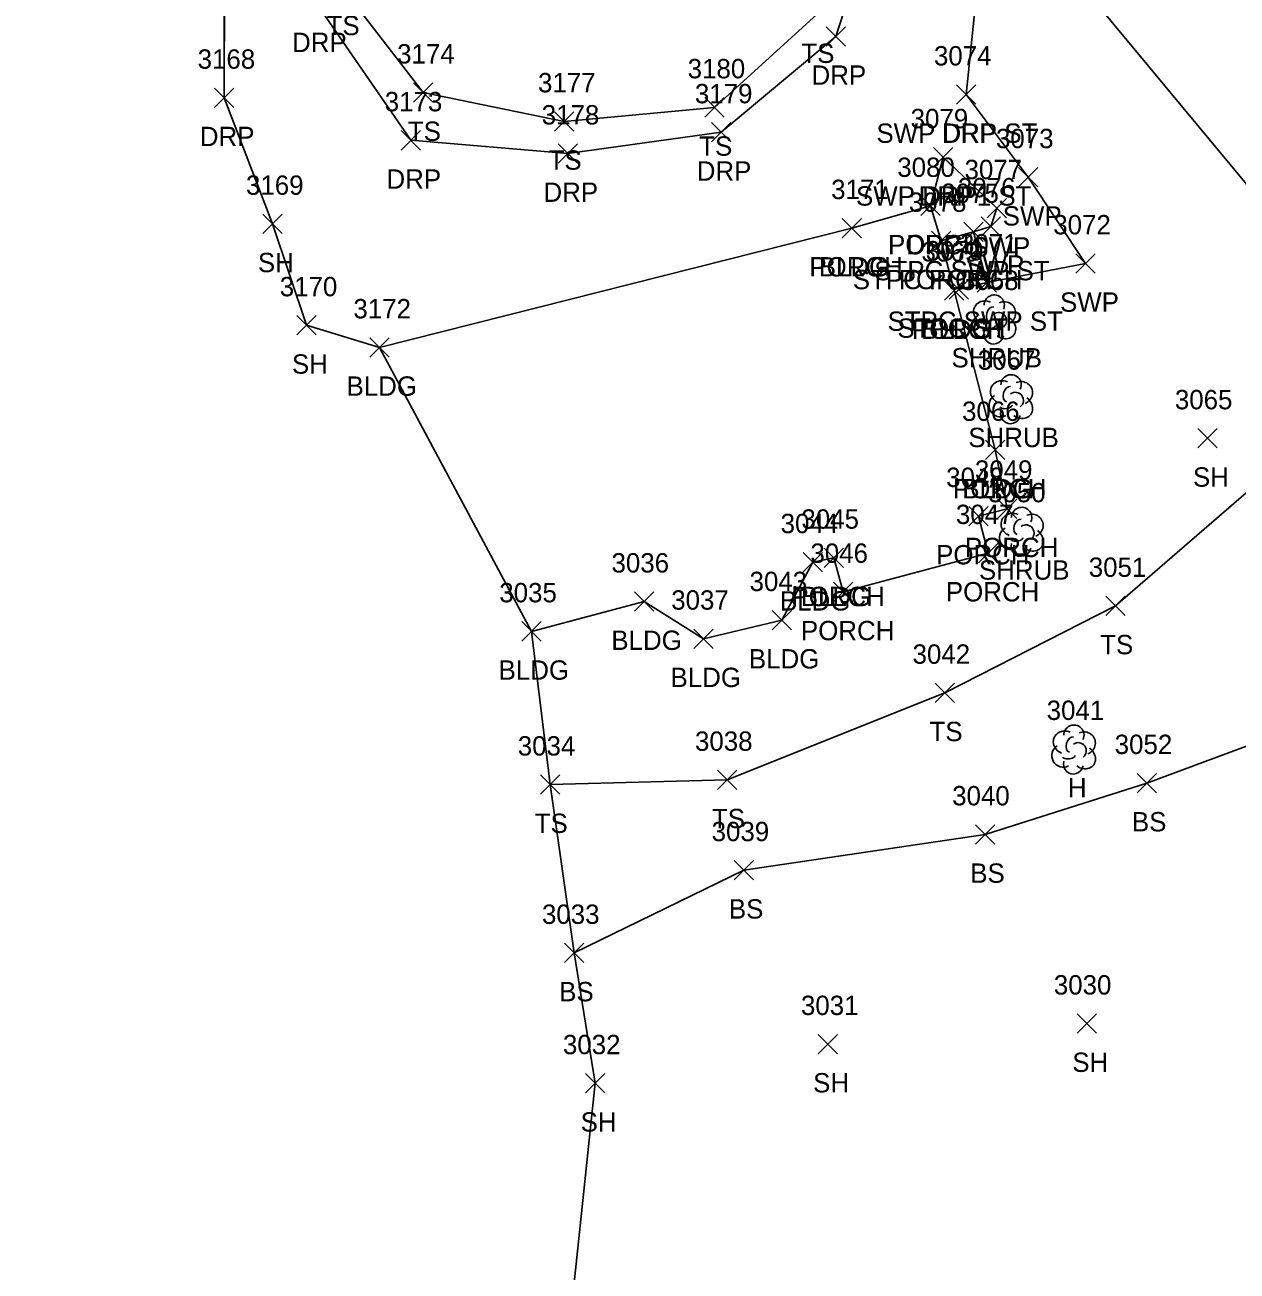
# Model space of a CAD drawing. Extents: x 1509053 to 1511576, y 400838 to 402572.
# Drawn here: x 1509560.1 to 1509685.4, y 401585.4 to 401714.2 of the extents above; entities that cross this region are included whole.
import ezdxf

# ---------------------------------------------------------------- set-up
doc = ezdxf.new("R2010")
doc.units = 0
for name, color, linetype in [('L_A', 7, 'Continuous'), ('L_I', 7, 'Continuous'), ('L_TIC', 7, 'Continuous'), ('LAWA', 7, 'Continuous'), ('LBC', 7, 'Continuous'), ('LBF', 7, 'Continuous'), ('LELB', 7, 'Continuous'), ('LSH', 7, 'Continuous'), ('LSOGP', 7, 'Continuous'), ('LTD', 7, 'Continuous'), ('R_A', 7, 'Continuous'), ('R_I', 7, 'Continuous'), ('R_TIC', 7, 'Continuous'), ('RDP', 7, 'Continuous'), ('RSW', 7, 'Continuous')]:
    doc.layers.add(name, color=color, linetype=linetype)

msp = doc.modelspace()

# ---------------------------------------------------------------- linework, layer by layer
at = {"layer": 'L_TIC'}
for points in [[(1509600.28, 401706.22), (1509602.28, 401708.22)], [(1509602.28, 401706.22), (1509600.28, 401708.22)], [(1509630.39, 401704.69), (1509632.39, 401706.69)], [(1509632.39, 401704.69), (1509630.39, 401706.69)], [(1509614.83, 401703.24), (1509616.83, 401705.24)], [(1509616.83, 401703.24), (1509614.83, 401705.24)], [(1509652.7, 401694.5), (1509654.7, 401696.5)], [(1509654.7, 401694.5), (1509652.7, 401696.5)], [(1509584.71, 401692.65), (1509586.71, 401694.65)], [(1509586.71, 401692.65), (1509584.71, 401694.65)], [(1509644.57, 401692.21), (1509646.57, 401694.21)], [(1509646.57, 401692.21), (1509644.57, 401694.21)], [(1509644.57, 401692.21), (1509646.57, 401694.21)], [(1509646.57, 401692.21), (1509644.57, 401694.21)], [(1509657.16, 401691.81), (1509659.16, 401693.81)], [(1509659.16, 401691.81), (1509657.16, 401693.81)], [(1509653.82, 401690.89), (1509655.82, 401692.89)], [(1509655.82, 401690.89), (1509653.82, 401692.89)], [(1509653.82, 401690.89), (1509655.82, 401692.89)], [(1509655.82, 401690.89), (1509653.82, 401692.89)], [(1509655.65, 401685.87), (1509657.65, 401687.87)], [(1509657.65, 401685.87), (1509655.65, 401687.87)], [(1509658.53, 401686.59), (1509660.53, 401688.59)], [(1509660.53, 401686.59), (1509658.53, 401688.59)], [(1509655.17, 401685.76), (1509657.17, 401687.76)], [(1509657.17, 401685.76), (1509655.17, 401687.76)], [(1509655.17, 401685.76), (1509657.17, 401687.76)], [(1509657.17, 401685.76), (1509655.17, 401687.76)], [(1509588.22, 401682.16), (1509590.22, 401684.16)], [(1509590.22, 401682.16), (1509588.22, 401684.16)], [(1509595.75, 401679.88), (1509597.75, 401681.88)], [(1509597.75, 401679.88), (1509595.75, 401681.88)], [(1509681.35, 401670.48), (1509683.35, 401672.48)], [(1509683.35, 401670.48), (1509681.35, 401672.48)], [(1509659.41, 401669.28), (1509661.41, 401671.28)], [(1509661.41, 401669.28), (1509659.41, 401671.28)], [(1509659.41, 401669.28), (1509661.41, 401671.28)], [(1509661.41, 401669.28), (1509659.41, 401671.28)], [(1509660.65, 401663.2), (1509662.65, 401665.2)], [(1509662.65, 401663.2), (1509660.65, 401665.2)], [(1509657.67, 401662.45), (1509659.67, 401664.45)], [(1509659.67, 401662.45), (1509657.67, 401664.45)], [(1509640.56, 401657.68), (1509642.56, 401659.68)], [(1509642.56, 401657.68), (1509640.56, 401659.68)], [(1509642.71, 401658.14), (1509644.71, 401660.14)], [(1509644.71, 401658.14), (1509642.71, 401660.14)], [(1509642.71, 401658.14), (1509644.71, 401660.14)], [(1509644.71, 401658.14), (1509642.71, 401660.14)], [(1509658.68, 401658.62), (1509660.68, 401660.62)], [(1509660.68, 401658.62), (1509658.68, 401660.62)], [(1509643.7, 401654.61), (1509645.7, 401656.61)], [(1509645.7, 401654.61), (1509643.7, 401656.61)], [(1509623.13, 401653.61), (1509625.13, 401655.61)], [(1509625.13, 401653.61), (1509623.13, 401655.61)], [(1509671.84, 401653.16), (1509673.84, 401655.16)], [(1509673.84, 401653.16), (1509671.84, 401655.16)], [(1509637.35, 401651.69), (1509639.35, 401653.69)], [(1509639.35, 401651.69), (1509637.35, 401653.69)], [(1509611.48, 401650.53), (1509613.48, 401652.53)], [(1509613.48, 401650.53), (1509611.48, 401652.53)], [(1509629.25, 401649.77), (1509631.25, 401651.77)], [(1509631.25, 401649.77), (1509629.25, 401651.77)], [(1509654.2, 401644.18), (1509656.2, 401646.18)], [(1509656.2, 401644.18), (1509654.2, 401646.18)], [(1509613.39, 401634.69), (1509615.39, 401636.69)], [(1509615.39, 401634.69), (1509613.39, 401636.69)], [(1509631.71, 401635.18), (1509633.71, 401637.18)], [(1509633.71, 401635.18), (1509631.71, 401637.18)], [(1509675.08, 401634.85), (1509677.08, 401636.85)], [(1509677.08, 401634.85), (1509675.08, 401636.85)], [(1509658.37, 401629.54), (1509660.37, 401631.54)], [(1509660.37, 401629.54), (1509658.37, 401631.54)], [(1509633.43, 401625.84), (1509635.43, 401627.84)], [(1509635.43, 401625.84), (1509633.43, 401627.84)], [(1509615.88, 401617.29), (1509617.88, 401619.29)], [(1509617.88, 401617.29), (1509615.88, 401619.29)], [(1509668.88, 401609.99), (1509670.88, 401611.99)], [(1509670.88, 401609.99), (1509668.88, 401611.99)], [(1509642.09, 401607.87), (1509644.09, 401609.87)], [(1509644.09, 401607.87), (1509642.09, 401609.87)], [(1509618.06, 401603.82), (1509620.06, 401605.82)], [(1509620.06, 401603.82), (1509618.06, 401605.82)]]:
    msp.add_lwpolyline(points, dxfattribs=at)
at = {"layer": 'LAWA'}
msp.add_lwpolyline([(1509638.88, 401488.13), (1509666.35, 401492.77), (1509693.47, 401489.31), (1509706.73, 401489.66), (1509714.33, 401510.79), (1509715.13, 401545.88), (1509713.34, 401580.23), (1509712.38, 401615.78), (1509710.87, 401643.63), (1509696.77, 401674.88), (1509690.26, 401693.05), (1509667.45, 401720.56), (1509662.48, 401743.44), (1509649.82, 401764.29), (1509628.65, 401784.18), (1509611.29, 401798.2), (1509592.85, 401815.68), (1509576.11, 401831.25), (1509568.72, 401841.78), (1509569.85, 401855.18), (1509582.24, 401868.06), (1509599.14, 401876.59), (1509619.4, 401883.23)], dxfattribs=at)
at = {"layer": 'LBC'}
for points in [[(1509645.57, 401693.21), (1509596.75, 401680.88)], [(1509660.41, 401670.28), (1509656.17, 401686.76)], [(1509612.48, 401651.53), (1509624.13, 401654.61), (1509630.25, 401650.77), (1509638.35, 401652.69), (1509641.56, 401658.68), (1509643.71, 401659.14)]]:
    msp.add_lwpolyline(points, dxfattribs=at)
at = {"layer": 'LBF'}
for points in [[(1509656.17, 401686.76), (1509654.82, 401691.89), (1509653.7, 401695.5), (1509645.57, 401693.21)], [(1509656.65, 401686.87), (1509659.53, 401687.59), (1509658.16, 401692.81), (1509654.82, 401691.89)], [(1509643.71, 401659.14), (1509644.7, 401655.61), (1509659.68, 401659.62), (1509658.67, 401663.45), (1509661.65, 401664.2), (1509660.41, 401670.28)]]:
    msp.add_lwpolyline(points, dxfattribs=at)
at = {"layer": 'LELB'}
for points in [[(1509601.28, 401707.22), (1509615.83, 401704.24), (1509631.39, 401705.69), (1509641.95, 401715.28), (1509646.3, 401727.1), (1509643.65, 401741.92), (1509634.43, 401756.65), (1509616.45, 401773.63), (1509604.1, 401783.09), (1509598.27, 401760.84), (1509593.29, 401737.02), (1509592.88, 401718.15)], [(1509592.88, 401718.15), (1509601.28, 401707.22)], [(1509614.39, 401635.69), (1509632.71, 401636.18), (1509655.2, 401645.18), (1509672.84, 401654.16), (1509696.77, 401674.88)], [(1509616.88, 401618.29), (1509634.43, 401626.84), (1509659.37, 401630.54), (1509676.08, 401635.85), (1509695.63, 401643.11)]]:
    msp.add_lwpolyline(points, dxfattribs=at)
at = {"layer": 'LSH'}
for p, q in [((1509660.25, 401683.81), (1509660.25, 401683.81)), ((1509660.25, 401683.81), (1509660.25, 401683.81)), ((1509661.99, 401675.57), (1509661.99, 401675.57)), ((1509661.99, 401675.57), (1509661.99, 401675.57)), ((1509663.09, 401661.87), (1509663.09, 401661.87)), ((1509663.09, 401661.87), (1509663.09, 401661.87))]:
    msp.add_line(p, q, dxfattribs=at)
for centre in [(1509660.3, 401685.25), (1509662.04, 401677.01), (1509663.13, 401663.3)]:
    msp.add_arc(centre, 1.05, 335.5272, 180.9563, dxfattribs=at)
for centre, major_axis, ratio, start_param, end_param in [((1509659.46, 401684.48), (1.21, -0.51), 0.895232, 1.570796, 4.712389), ((1509661.29, 401684.4), (-1.14, -0.48), 0.949671, 1.570796, 4.712389), ((1509659.17, 401683.1), (0.58, -1.04), 0.959034, 3.141593, 6.283185), ((1509660.04, 401684.27), (-0.208, -0.792), 0.645439, 3.141593, 6.283185), ((1509660.75, 401683.65), (-0.5, 0.667), 0.989748, 3.141593, 6.283185), ((1509659.79, 401683.06), (-0.625, -0.083), 0.423636, 0, 3.141593), ((1509661.25, 401682.98), (-1.09, 0.79), 0.841452, 1.570796, 4.712389), ((1509660.25, 401682.31), (0.26, 1.06), 0.942809, 1.570796, 4.712389), ((1509661.2, 401676.24), (1.21, -0.51), 0.895232, 1.570796, 4.712389), ((1509661.78, 401676.03), (-0.208, -0.792), 0.645439, 3.141593, 6.283185), ((1509662.49, 401675.41), (-0.5, 0.667), 0.989748, 3.141593, 6.283185), ((1509663.03, 401676.16), (-1.14, -0.48), 0.949671, 1.570796, 4.712389), ((1509660.91, 401674.87), (0.58, -1.04), 0.959034, 3.141593, 6.283185), ((1509662.99, 401674.74), (-1.09, 0.79), 0.841452, 1.570796, 4.712389), ((1509661.99, 401674.07), (0.26, 1.06), 0.942809, 1.570796, 4.712389), ((1509661.53, 401674.82), (-0.625, -0.083), 0.423636, 0, 3.141593), ((1509662.3, 401662.53), (1.21, -0.51), 0.895232, 1.570796, 4.712389), ((1509664.13, 401662.45), (-1.14, -0.48), 0.949671, 1.570796, 4.712389), ((1509662, 401661.16), (0.58, -1.04), 0.959034, 3.141593, 6.283185), ((1509662.88, 401662.32), (-0.208, -0.792), 0.645439, 3.141593, 6.283185), ((1509663.59, 401661.7), (-0.5, 0.667), 0.989748, 3.141593, 6.283185), ((1509662.63, 401661.12), (-0.625, -0.083), 0.423636, 0, 3.141593), ((1509664.09, 401661.03), (-1.09, 0.79), 0.841452, 1.570796, 4.712389), ((1509663.09, 401660.37), (0.26, 1.06), 0.942809, 1.570796, 4.712389)]:
    msp.add_ellipse(centre, major_axis=major_axis, ratio=ratio, start_param=start_param, end_param=end_param, dxfattribs=at)
at = {"layer": 'LSOGP'}
msp.add_lwpolyline([(1509580.73, 401718.39), (1509580.72, 401712.53), (1509580.7, 401706.68), (1509585.71, 401693.65), (1509589.22, 401683.16), (1509596.75, 401680.88), (1509612.48, 401651.53), (1509614.39, 401635.69), (1509616.88, 401618.29), (1509619.06, 401604.82), (1509615.52, 401571.4)], dxfattribs=at)
at = {"layer": 'LTD'}
msp.add_line((1509668.49, 401639.37), (1509668.49, 401639.37), dxfattribs=at)
msp.add_line((1509668.49, 401639.37), (1509668.49, 401639.37), dxfattribs=at)
msp.add_arc((1509668.53, 401640.8), 1.05, 335.5272, 180.9563, dxfattribs=at)
for centre, major_axis, ratio, start_param, end_param in [((1509667.7, 401640.03), (1.21, -0.51), 0.895232, 1.570796, 4.712389), ((1509668.28, 401639.82), (-0.208, -0.792), 0.645439, 3.141593, 6.283185), ((1509669.53, 401639.95), (-1.14, -0.48), 0.949671, 1.570796, 4.712389), ((1509667.4, 401638.66), (0.58, -1.04), 0.959034, 3.141593, 6.283185), ((1509668.99, 401639.2), (-0.5, 0.667), 0.989748, 3.141593, 6.283185), ((1509669.49, 401638.53), (-1.09, 0.79), 0.841452, 1.570796, 4.712389), ((1509668.49, 401637.87), (0.26, 1.06), 0.942809, 1.570796, 4.712389), ((1509668.03, 401638.62), (-0.625, -0.083), 0.423636, 0, 3.141593)]:
    msp.add_ellipse(centre, major_axis=major_axis, ratio=ratio, start_param=start_param, end_param=end_param, dxfattribs=at)
at = {"layer": 'R_TIC'}
for points in [[(1509642.93, 401712.02), (1509644.93, 401714.02)], [(1509644.93, 401712.02), (1509642.93, 401714.02)], [(1509579.7, 401705.68), (1509581.7, 401707.68)], [(1509581.7, 401705.68), (1509579.7, 401707.68)], [(1509656.41, 401706.02), (1509658.41, 401708.02)], [(1509658.41, 401706.02), (1509656.41, 401708.02)], [(1509656.41, 401706.02), (1509658.41, 401708.02)], [(1509658.41, 401706.02), (1509656.41, 401708.02)], [(1509631.07, 401702.11), (1509633.07, 401704.11)], [(1509633.07, 401702.11), (1509631.07, 401704.11)], [(1509599, 401701.28), (1509601, 401703.28)], [(1509601, 401701.28), (1509599, 401703.28)], [(1509615.22, 401699.92), (1509617.22, 401701.92)], [(1509617.22, 401699.92), (1509615.22, 401701.92)], [(1509654.01, 401699.53), (1509656.01, 401701.53)], [(1509656.01, 401699.53), (1509654.01, 401701.53)], [(1509654.01, 401699.53), (1509656.01, 401701.53)], [(1509656.01, 401699.53), (1509654.01, 401701.53)], [(1509662.82, 401697.47), (1509664.82, 401699.47)], [(1509664.82, 401697.47), (1509662.82, 401699.47)], [(1509652.7, 401694.5), (1509654.7, 401696.5)], [(1509654.7, 401694.5), (1509652.7, 401696.5)], [(1509659.57, 401694.27), (1509661.57, 401696.27)], [(1509661.57, 401694.27), (1509659.57, 401696.27)], [(1509658.95, 401692.39), (1509660.95, 401694.39)], [(1509660.95, 401692.39), (1509658.95, 401694.39)], [(1509657.16, 401691.81), (1509659.16, 401693.81)], [(1509659.16, 401691.81), (1509657.16, 401693.81)], [(1509668.74, 401688.56), (1509670.74, 401690.56)], [(1509670.74, 401688.56), (1509668.74, 401690.56)], [(1509658.53, 401686.59), (1509660.53, 401688.59)], [(1509660.53, 401686.59), (1509658.53, 401688.59)]]:
    msp.add_lwpolyline(points, dxfattribs=at)
at = {"layer": 'RDP'}
for points in [[(1509572.43, 401913.76), (1509571.87, 401895.84), (1509563.03, 401875.91), (1509553.74, 401858.01), (1509556.14, 401835.6), (1509571.23, 401816.18), (1509583.76, 401803.06), (1509589.35, 401790.3), (1509589.12, 401773.24), (1509584.51, 401748.72), (1509580.76, 401730.09), (1509580.7, 401706.68)], [(1509657.41, 401707.02), (1509658.95, 401722.11), (1509659.43, 401736.67), (1509654.34, 401752.12), (1509646.68, 401762.21), (1509626.54, 401780.34), (1509601.43, 401800.74), (1509589.45, 401812.5), (1509573.07, 401828.07), (1509565.22, 401840.56), (1509563.11, 401852.67), (1509569.22, 401864.7), (1509579.4, 401875.5), (1509597.32, 401883.76), (1509619.81, 401887.87)], [(1509600, 401702.28), (1509616.22, 401700.92), (1509632.07, 401703.11), (1509643.93, 401713.02), (1509648.45, 401726.97), (1509646.97, 401743.37), (1509636.64, 401758.29), (1509617.59, 401775.35), (1509604.11, 401785.41), (1509600.8, 401784.04), (1509595.56, 401761.91), (1509590.55, 401737.08), (1509590.23, 401716.41)], [(1509590.23, 401716.41), (1509600, 401702.28)], [(1509655.01, 401700.53), (1509653.7, 401695.5)]]:
    msp.add_lwpolyline(points, dxfattribs=at)
at = {"layer": 'RSW'}
for points in [[(1509659.53, 401687.59), (1509669.74, 401689.56), (1509663.82, 401698.47), (1509657.41, 401707.02)], [(1509658.16, 401692.81), (1509659.95, 401693.39), (1509660.57, 401695.27), (1509655.01, 401700.53)]]:
    msp.add_lwpolyline(points, dxfattribs=at)

# ---------------------------------------------------------------- texts
at = {"layer": 'L_A'}
for s, p in [('TS', (1509591.29, 401713.15)), ('TS', (1509640.36, 401710.28)), ('TS', (1509599.69, 401702.22)), ('TS', (1509629.8, 401700.69)), ('TS', (1509614.24, 401699.24)), ('PORCH', (1509649.32, 401690.5)), ('SH', (1509584.19, 401688.65)), ('PORCH', (1509641.19, 401688.21)), ('BLDG', (1509642.16, 401688.21)), ('STPC SWP ST', (1509647.9, 401687.81)), ('STPC PORCH', (1509645.68, 401686.89)), ('PORCH', (1509650.44, 401686.89)), ('STPC SWP ST', (1509649.27, 401682.59)), ('STPC ST', (1509650.29, 401681.87)), ('PORCH', (1509651.79, 401681.76)), ('BLDG', (1509652.76, 401681.76)), ('SH', (1509587.71, 401678.16)), ('SHRUB', (1509655.88, 401678.81)), ('BLDG', (1509593.35, 401675.88)), ('SHRUB', (1509657.62, 401670.57)), ('PORCH', (1509656.03, 401665.28)), ('BLDG', (1509657, 401665.28)), ('SH', (1509680.84, 401666.48)), ('PORCH', (1509657.27, 401659.2)), ('PORCH', (1509654.29, 401658.45)), ('SHRUB', (1509658.72, 401656.87)), ('BLDG', (1509638.15, 401653.68)), ('PORCH', (1509639.33, 401654.14)), ('BLDG', (1509640.3, 401654.14)), ('PORCH', (1509655.3, 401654.62)), ('PORCH', (1509640.32, 401650.61)), ('BLDG', (1509620.72, 401649.61)), ('TS', (1509671.25, 401649.16)), ('BLDG', (1509634.94, 401647.69)), ('BLDG', (1509609.07, 401646.53)), ('BLDG', (1509626.84, 401645.77)), ('TS', (1509653.61, 401640.18)), ('H', (1509667.92, 401634.37)), ('TS', (1509612.8, 401630.69)), ('TS', (1509631.12, 401631.18)), ('BS', (1509674.53, 401630.85)), ('BS', (1509657.82, 401625.54)), ('BS', (1509632.87, 401621.84)), ('BS', (1509615.33, 401613.29)), ('SH', (1509668.37, 401605.99)), ('SH', (1509641.58, 401603.87)), ('SH', (1509617.55, 401599.82))]:
    msp.add_text(s, height=2, dxfattribs=at).set_placement(p)
at = {"layer": 'L_I'}
for s, p in [('3174', (1509598.58, 401710.22)), ('3180', (1509628.61, 401708.69)), ('3177', (1509613.14, 401707.24)), ('3080', (1509650.28, 401698.5)), ('3169', (1509582.96, 401696.65)), ('3171', (1509643.44, 401696.21)), ('3171', (1509643.44, 401696.21)), ('3078', (1509651.48, 401694.89)), ('3078', (1509651.48, 401694.89)), ('3075', (1509654.83, 401695.81)), ('3069', (1509652.78, 401689.76)), ('3069', (1509652.78, 401689.76)), ('3070', (1509653.22, 401689.87)), ('3071', (1509656.76, 401690.59)), ('3170', (1509586.45, 401686.16)), ('3068', (1509656.87, 401686.81)), ('3172', (1509594.06, 401683.88)), ('3067', (1509658.6, 401678.57)), ('3065', (1509678.97, 401674.48)), ('3066', (1509656.97, 401673.28)), ('3066', (1509656.97, 401673.28)), ('3049', (1509658.3, 401667.2)), ('3048', (1509655.33, 401666.45)), ('3050', (1509659.66, 401664.87)), ('3044', (1509638.22, 401661.68)), ('3045', (1509640.37, 401662.14)), ('3045', (1509640.37, 401662.14)), ('3047', (1509656.34, 401662.62)), ('3036', (1509620.74, 401657.61)), ('3046', (1509641.3, 401658.61)), ('3051', (1509670.07, 401657.16)), ('3043', (1509635.01, 401655.69)), ('3035', (1509609.14, 401654.53)), ('3037', (1509626.91, 401653.77)), ('3042', (1509651.86, 401648.18)), ('3041', (1509665.72, 401642.37)), ('3034', (1509611.05, 401638.69)), ('3038', (1509629.37, 401639.18)), ('3052', (1509672.75, 401638.85)), ('3040', (1509655.95, 401633.54)), ('3039', (1509631.09, 401629.84)), ('3033', (1509613.55, 401621.29)), ('3030', (1509666.46, 401613.99)), ('3031', (1509640.32, 401611.87)), ('3032', (1509615.72, 401607.82))]:
    msp.add_text(s, height=2, dxfattribs=at).set_placement(p)
at = {"layer": 'R_A'}
for s, p in [('DRP', (1509587.72, 401711.41)), ('DRP', (1509641.42, 401708.02)), ('DRP', (1509578.19, 401701.68)), ('SWP DRP ST', (1509648.12, 401702.02)), ('DRP', (1509654.89, 401702.02)), ('DRP', (1509629.55, 401698.11)), ('DRP', (1509597.48, 401697.28)), ('DRP', (1509613.71, 401695.92)), ('SWP DRP1 ST', (1509646.01, 401695.53)), ('DRP', (1509652.49, 401695.53)), ('SWP', (1509661.18, 401693.47)), ('DRP', (1509651.19, 401690.5)), ('SWP', (1509657.93, 401690.27)), ('STPC SWP ST', (1509647.9, 401687.81)), ('SWP', (1509657.31, 401688.39)), ('SWP', (1509667.1, 401684.56)), ('STPC SWP ST', (1509649.27, 401682.59))]:
    msp.add_text(s, height=2, dxfattribs=at).set_placement(p)
at = {"layer": 'R_I'}
for s, p in [('3168', (1509577.96, 401709.68)), ('3074', (1509654.07, 401710.02)), ('3074', (1509654.07, 401710.02)), ('3173', (1509597.3, 401705.28)), ('3179', (1509629.36, 401706.11)), ('3178', (1509613.53, 401703.92)), ('3079', (1509651.66, 401703.53)), ('3079', (1509651.66, 401703.53)), ('3073', (1509660.48, 401701.47)), ('3080', (1509650.28, 401698.5)), ('3077', (1509657.23, 401698.27)), ('3076', (1509656.55, 401696.39)), ('3075', (1509654.83, 401695.81)), ('3072', (1509666.4, 401692.56)), ('3071', (1509656.76, 401690.59))]:
    msp.add_text(s, height=2, dxfattribs=at).set_placement(p)

doc.saveas('drawing.dxf')
